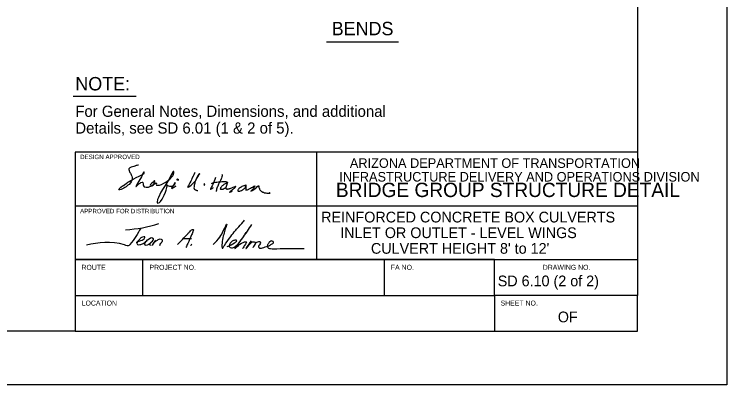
# Model space of a CAD drawing. Extents: x -0.08 to 2.83, y -0.03 to 1.92.
# Drawn here: x 2.003 to 2.833, y 0 to 0.431 of the extents above; entities that cross this region are included whole.
import ezdxf

# ---------------------------------------------------------------- set-up
doc = ezdxf.new("R2010")
doc.units = 0
for name, color, linetype in [('55', 7, 'Continuous'), ('57', 7, 'Continuous'), ('62', 7, 'Continuous'), ('63', 7, 'Continuous')]:
    doc.layers.add(name, color=color, linetype=linetype)

msp = doc.modelspace()

# ---------------------------------------------------------------- linework, layer by layer
at = {"layer": '57'}
for p, q in [((2.36678, 0.39921), (2.45047, 0.39921)), ((2.07131, 0.33607), (2.14477, 0.33607))]:
    msp.add_line(p, q, dxfattribs=at)
for points in [[(2.14765, 0.25562), (2.14682, 0.25571), (2.14575, 0.25542), (2.14487, 0.25532), (2.14398, 0.25503), (2.14311, 0.25475), (2.14203, 0.25429), (2.14043, 0.25389), (2.13901, 0.25331), (2.13813, 0.25284), (2.13758, 0.25263), (2.13706, 0.2524), (2.13655, 0.25191), (2.13637, 0.25143), (2.13634, 0.25038), (2.13646, 0.24988), (2.13669, 0.24909), (2.13707, 0.24825), (2.13754, 0.24729), (2.13802, 0.24626), (2.13848, 0.24568), (2.1391, 0.24444), (2.13948, 0.24359), (2.13985, 0.24285), (2.14011, 0.24143), (2.14019, 0.24048), (2.14006, 0.2395), (2.13967, 0.23801), (2.13887, 0.23634), (2.13823, 0.23519), (2.13663, 0.23333), (2.13514, 0.23225), (2.13328, 0.23066), (2.13172, 0.22974), (2.13035, 0.22879), (2.12878, 0.22803), (2.12732, 0.22727), (2.12575, 0.22684), (2.12502, 0.22692), (2.12462, 0.22757), (2.12482, 0.22803), (2.12536, 0.22854), (2.12583, 0.22911), (2.12687, 0.23003), (2.12901, 0.23148), (2.12993, 0.23223), (2.13153, 0.23337), (2.13326, 0.23448), (2.13516, 0.23574), (2.13681, 0.23665), (2.14133, 0.23946), (2.14564, 0.24158), (2.14763, 0.24265), (2.14977, 0.24371), (2.15138, 0.24446), (2.15266, 0.24523), (2.15357, 0.24588), (2.15395, 0.24653), (2.15403, 0.24774), (2.15357, 0.24792), (2.15339, 0.24772), (2.15326, 0.24744), (2.15189, 0.24408), (2.15104, 0.24225), (2.14793, 0.2371), (2.14615, 0.23392), (2.14537, 0.23259), (2.14456, 0.23092), (2.14471, 0.23073), (2.14621, 0.23237), (2.14786, 0.23379), (2.14933, 0.2349), (2.15041, 0.23553), (2.15025, 0.23554), (2.15166, 0.23596), (2.15233, 0.23575), (2.15248, 0.23551), (2.15292, 0.23413), (2.15298, 0.23275), (2.15347, 0.23157), (2.15416, 0.23064), (2.15662, 0.23007), (2.15903, 0.23008), (2.16063, 0.23083), (2.16326, 0.23175), (2.16493, 0.23298), (2.16588, 0.2341), (2.1662, 0.23616), (2.16645, 0.23743), (2.16619, 0.23773), (2.16568, 0.23744), (2.16444, 0.2361), (2.16299, 0.23465), (2.16243, 0.234), (2.16167, 0.23323), (2.16131, 0.23193), (2.16152, 0.23111), (2.16315, 0.23186), (2.16495, 0.23312), (2.16659, 0.23422), (2.1675, 0.23485)], [(2.1675, 0.23485), (2.16768, 0.23502), (2.16803, 0.23499), (2.16833, 0.23428), (2.16809, 0.23323), (2.1685, 0.23253), (2.16938, 0.23231), (2.17073, 0.23226), (2.17219, 0.23262), (2.17432, 0.23335), (2.17707, 0.2347), (2.17923, 0.23592), (2.18111, 0.23698), (2.18401, 0.23935), (2.18673, 0.24251), (2.1874, 0.24345), (2.18795, 0.24413), (2.18885, 0.24684), (2.18861, 0.24817), (2.18803, 0.24838), (2.18525, 0.24365), (2.18363, 0.24013), (2.17856, 0.23217), (2.17642, 0.22845), (2.17367, 0.22436), (2.17077, 0.21821), (2.16978, 0.21578), (2.16922, 0.21263), (2.16931, 0.21192), (2.17007, 0.21144), (2.17188, 0.21228), (2.17301, 0.21331), (2.17493, 0.21608), (2.17752, 0.22087), (2.17895, 0.22416), (2.17971, 0.22647), (2.18065, 0.22981), (2.18078, 0.23184), (2.18067, 0.23323), (2.18006, 0.23363), (2.17971, 0.23383), (2.17996, 0.23312), (2.18067, 0.23272), (2.18133, 0.23216), (2.18235, 0.23173), (2.18352, 0.2313), (2.18407, 0.23126), (2.18577, 0.23115), (2.18651, 0.23125), (2.18788, 0.23169), (2.18906, 0.23271), (2.18935, 0.23298), (2.19013, 0.23462), (2.19023, 0.23513), (2.18976, 0.23544), (2.18843, 0.23244), (2.1867, 0.2305), (2.18629, 0.22968), (2.18597, 0.22898), (2.18621, 0.22854), (2.18855, 0.23002), (2.18946, 0.2305), (2.19059, 0.23118), (2.19141, 0.23178)], [(2.21321, 0.24728), (2.21278, 0.24633), (2.21192, 0.2446), (2.21109, 0.24289), (2.20987, 0.24003), (2.20924, 0.23883), (2.20839, 0.23714), (2.20749, 0.23532), (2.20656, 0.23362), (2.20585, 0.23209), (2.20522, 0.23093), (2.20498, 0.23028), (2.20498, 0.22995), (2.20514, 0.22994), (2.20538, 0.22984), (2.20569, 0.22998), (2.20645, 0.23048), (2.20741, 0.23118), (2.20881, 0.23228), (2.21007, 0.23343), (2.2113, 0.23468), (2.21223, 0.23566), (2.21333, 0.23669), (2.21398, 0.23754), (2.2148, 0.23898), (2.21596, 0.24094), (2.21666, 0.24203), (2.21782, 0.24413), (2.21837, 0.24483), (2.21887, 0.24558), (2.21893, 0.24581), (2.21882, 0.24594), (2.21866, 0.246), (2.21854, 0.24593), (2.21806, 0.24521), (2.21715, 0.24405), (2.21599, 0.24204), (2.21572, 0.24131), (2.21528, 0.24042), (2.21488, 0.23963), (2.21393, 0.23749), (2.21329, 0.23598), (2.21302, 0.23478), (2.21269, 0.23374), (2.21253, 0.23244), (2.21229, 0.23068), (2.21218, 0.22945), (2.21231, 0.22828), (2.21257, 0.22781), (2.21318, 0.22732), (2.21379, 0.22691), (2.21433, 0.22667), (2.21497, 0.22648), (2.21556, 0.2264), (2.21619, 0.22636), (2.21665, 0.22637)], [(2.23711, 0.24121), (2.23674, 0.24001), (2.23642, 0.239), (2.23579, 0.23723), (2.23502, 0.23525), (2.23462, 0.2345), (2.23406, 0.23333), (2.23329, 0.23174), (2.23267, 0.23059), (2.23222, 0.22966), (2.23172, 0.22875), (2.2315, 0.22823), (2.23146, 0.2278), (2.23159, 0.22758), (2.23184, 0.22757), (2.232, 0.22763), (2.23258, 0.22801), (2.23313, 0.22838), (2.23337, 0.22858), (2.23364, 0.22878), (2.23378, 0.22887), (2.23399, 0.22905), (2.23421, 0.22928), (2.23441, 0.22947), (2.23448, 0.22961), (2.23467, 0.22983)], [(2.24473, 0.24483), (2.24497, 0.24428), (2.24498, 0.24372), (2.24493, 0.24321), (2.24468, 0.24225), (2.24431, 0.24076), (2.24388, 0.23971), (2.24318, 0.23801), (2.24267, 0.23695), (2.24213, 0.23588), (2.24099, 0.23343), (2.24057, 0.23259), (2.23951, 0.23037), (2.23933, 0.22998), (2.23898, 0.22908), (2.23857, 0.22768), (2.23835, 0.22672), (2.23821, 0.22563), (2.23811, 0.22523)], [(2.19468, 0.23875), (2.1943, 0.23878), (2.19381, 0.23888), (2.19338, 0.23913), (2.19307, 0.23928), (2.19284, 0.23933), (2.19253, 0.23933), (2.19238, 0.23916), (2.1922, 0.23895), (2.19217, 0.23886), (2.19224, 0.23861), (2.19245, 0.23854), (2.19273, 0.23851), (2.19302, 0.23849), (2.1935, 0.23855), (2.19382, 0.23856), (2.19419, 0.23856), (2.19455, 0.23867), (2.19471, 0.23872)], [(2.22443, 0.23244), (2.22472, 0.23308), (2.2246, 0.23376), (2.22436, 0.23406), (2.22408, 0.23412), (2.22398, 0.23393), (2.22388, 0.23324), (2.224, 0.23256), (2.22423, 0.23234), (2.22434, 0.2322), (2.22443, 0.23224), (2.2244, 0.23238)], [(2.23248, 0.23456), (2.23325, 0.23476), (2.2342, 0.23501), (2.23568, 0.23543), (2.23742, 0.23576), (2.23878, 0.23593), (2.24092, 0.23616), (2.24296, 0.23643), (2.24483, 0.23658), (2.24631, 0.23661), (2.24751, 0.23662), (2.24815, 0.23658), (2.24954, 0.23651), (2.25052, 0.23638), (2.25088, 0.23621), (2.25113, 0.23568), (2.2507, 0.2337), (2.25061, 0.23341), (2.25006, 0.23176), (2.24968, 0.23083), (2.24923, 0.2298), (2.24903, 0.22937), (2.24881, 0.22913), (2.24855, 0.22885), (2.24788, 0.22845), (2.24669, 0.22782), (2.24572, 0.22757), (2.24486, 0.22728), (2.24453, 0.22723), (2.24402, 0.22721), (2.24346, 0.22738), (2.24333, 0.22753), (2.24326, 0.22773), (2.24329, 0.22813), (2.24333, 0.22875), (2.24351, 0.22929), (2.24369, 0.22982), (2.24413, 0.23055), (2.24473, 0.23118), (2.24562, 0.23205), (2.24626, 0.23258), (2.24677, 0.23295), (2.24743, 0.23348), (2.24812, 0.23387), (2.24898, 0.23437), (2.24957, 0.23468), (2.25026, 0.23503), (2.25053, 0.23503), (2.25075, 0.23493), (2.25082, 0.23468), (2.25057, 0.23343), (2.25053, 0.23315), (2.25026, 0.23215), (2.24986, 0.23102), (2.2495, 0.23), (2.24939, 0.2295), (2.24935, 0.22926), (2.24932, 0.22911), (2.24933, 0.22867), (2.24944, 0.22839), (2.24977, 0.2281), (2.2499, 0.22803), (2.25012, 0.22803), (2.2505, 0.22796), (2.25113, 0.22796), (2.25153, 0.22798), (2.25188, 0.22807), (2.25251, 0.22818), (2.25313, 0.22828), (2.25369, 0.22836), (2.25436, 0.22853), (2.25515, 0.22883), (2.25633, 0.22935), (2.25781, 0.22992), (2.25893, 0.23036), (2.25968, 0.23067), (2.26019, 0.23098), (2.2608, 0.23112), (2.26094, 0.23098), (2.26057, 0.23036), (2.26004, 0.22976), (2.25931, 0.22903), (2.25887, 0.22862), (2.25828, 0.22803), (2.25718, 0.22698), (2.25408, 0.22424), (2.25384, 0.22398), (2.25413, 0.22412), (2.25504, 0.22455), (2.25579, 0.22489), (2.25632, 0.22513), (2.25663, 0.22528)], [(2.27233, 0.23026), (2.27212, 0.2318), (2.27153, 0.23226), (2.27104, 0.23214), (2.26923, 0.23137), (2.2681, 0.23077), (2.26717, 0.23022), (2.26638, 0.22968), (2.26546, 0.22897), (2.26466, 0.22842), (2.26423, 0.22782), (2.26369, 0.2272), (2.26337, 0.22659), (2.26336, 0.22625), (2.26337, 0.22586), (2.26366, 0.22562), (2.26398, 0.22548), (2.26441, 0.22542), (2.26464, 0.22542), (2.26516, 0.22547), (2.26554, 0.22556), (2.2664, 0.22583), (2.26779, 0.22633), (2.26861, 0.22685), (2.26952, 0.22746), (2.27029, 0.22808), (2.27109, 0.22873), (2.27183, 0.22942), (2.27243, 0.23006), (2.27312, 0.23148), (2.27319, 0.23218), (2.27303, 0.23268), (2.27271, 0.23234), (2.27258, 0.23171), (2.27262, 0.23101), (2.27263, 0.22988), (2.27258, 0.22914), (2.27257, 0.22827), (2.27259, 0.22769), (2.27259, 0.22686), (2.27266, 0.22673), (2.27281, 0.22671), (2.27373, 0.22695), (2.27465, 0.22718), (2.27539, 0.22753), (2.2761, 0.22788), (2.27641, 0.22803), (2.27723, 0.22842), (2.27798, 0.22885), (2.27917, 0.22956), (2.28043, 0.2302), (2.28166, 0.23094), (2.28213, 0.23122), (2.28297, 0.23177), (2.28313, 0.23174), (2.28293, 0.23104), (2.28261, 0.23033), (2.28215, 0.22959), (2.28155, 0.22873), (2.28111, 0.22811), (2.27994, 0.22684), (2.27862, 0.22555), (2.27853, 0.22532), (2.27868, 0.22528), (2.28006, 0.22628), (2.28188, 0.22757), (2.28343, 0.22858), (2.28454, 0.22938), (2.28567, 0.23033), (2.28698, 0.23175), (2.28705, 0.23179), (2.28728, 0.23206), (2.28742, 0.23198), (2.28766, 0.23069), (2.2879, 0.22988), (2.28822, 0.22903), (2.28848, 0.22836), (2.28878, 0.22766), (2.28907, 0.22713), (2.28958, 0.22627), (2.28999, 0.22582), (2.29046, 0.22545), (2.29094, 0.22511), (2.29132, 0.22488), (2.29228, 0.2244), (2.29317, 0.22411), (2.29438, 0.22369), (2.29511, 0.22358), (2.29611, 0.22335), (2.29699, 0.22325), (2.29795, 0.22323), (2.29877, 0.22316), (2.29951, 0.22312), (2.30051, 0.22297), (2.30093, 0.22293), (2.30071, 0.22307), (2.30038, 0.22326), (2.30007, 0.22348), (2.29987, 0.2236)]]:
    msp.add_lwpolyline(points, dxfattribs=at)
msp.add_arc((2.12576, 0.32651), 0.14607, 272.67102, 288.18495, dxfattribs=at)
msp.add_ellipse((2.1597, 0.16674), major_axis=(0.00445, 0.00414), ratio=0.425517, dxfattribs=at)
for points in [[(2.23468, 0.16329), (2.24247, 0.17206), (2.2468, 0.17993), (2.25055, 0.18688), (2.24978, 0.18448), (2.24873, 0.18168), (2.24786, 0.17853), (2.24593, 0.17117), (2.24575, 0.15925), (2.24768, 0.16223), (2.25383, 0.17108), (2.25913, 0.17799), (2.26284, 0.18217), (2.26953, 0.18973), (2.27125, 0.19154)], [(2.27913, 0.18645), (2.26691, 0.16866), (2.26002, 0.15884), (2.27102, 0.16638), (2.27174, 0.16649), (2.27323, 0.16633), (2.27308, 0.16531), (2.27148, 0.1627), (2.26896, 0.15855)], [(2.15026, 0.18245), (2.13747, 0.1632), (2.13658, 0.16231), (2.13123, 0.16275), (2.08684, 0.16261)], [(2.19315, 0.16345), (2.19896, 0.16933), (2.20501, 0.17574), (2.20724, 0.17819), (2.20941, 0.1803), (2.21138, 0.18096), (2.2113, 0.17937), (2.21077, 0.17794), (2.20906, 0.17363), (2.20497, 0.16464), (2.20276, 0.16)], [(2.25098, 0.16082), (2.25957, 0.16531), (2.26102, 0.16633), (2.26204, 0.16779), (2.26175, 0.16822), (2.26001, 0.16837), (2.25666, 0.16706), (2.25405, 0.16415), (2.25332, 0.16197), (2.25332, 0.16095), (2.25581, 0.15961), (2.26008, 0.16091), (2.26408, 0.1646), (2.27308, 0.1773)], [(2.14468, 0.16595), (2.15189, 0.16856), (2.15402, 0.16987), (2.155, 0.1715), (2.155, 0.17216), (2.15369, 0.17232), (2.15108, 0.1715), (2.1483, 0.16889), (2.1465, 0.16676), (2.14569, 0.16464), (2.14634, 0.16333), (2.14912, 0.16317), (2.15298, 0.16457), (2.15512, 0.16583), (2.15712, 0.16742), (2.15716, 0.16742)], [(2.16416, 0.17088), (2.16467, 0.1696), (2.16316, 0.16671), (2.16115, 0.16432), (2.16077, 0.16281), (2.16153, 0.16206)], [(2.16731, 0.16847), (2.16582, 0.16612), (2.16341, 0.16218), (2.16591, 0.16562), (2.16907, 0.16797), (2.17045, 0.16897), (2.17488, 0.16916), (2.17524, 0.16783), (2.17478, 0.16626), (2.17294, 0.16391), (2.17196, 0.1618)], [(2.20019, 0.17022), (2.20269, 0.17029), (2.20533, 0.17015), (2.20922, 0.17029)], [(2.27878, 0.16743), (2.27342, 0.15912), (2.27381, 0.15951), (2.27965, 0.16591), (2.28139, 0.16656), (2.28339, 0.16597), (2.28369, 0.16421), (2.28271, 0.16235), (2.28114, 0.1599), (2.28349, 0.16333), (2.28546, 0.166), (2.28955, 0.16646), (2.28936, 0.16401), (2.28761, 0.1603), (2.28796, 0.15989), (2.28878, 0.1592), (2.29346, 0.1599), (2.29972, 0.16196), (2.30275, 0.16362), (2.30493, 0.16569), (2.30353, 0.16734), (2.30001, 0.16587), (2.29825, 0.16323), (2.29786, 0.16235), (2.29776, 0.16049), (2.30158, 0.15863), (2.30871, 0.15844), (2.34054, 0.15879)], [(2.20987, 0.16382), (2.20906, 0.16268), (2.20808, 0.16202)]]:
    msp.add_spline(points, degree=3, dxfattribs=at)
at = {"layer": '63'}
for p, q in [((2.83333, 1.83333), (2.83333, 0)), ((2.72918, 0.27077), (2.07387, 0.27077)), ((2.07387, 0.27077), (2.07387, 0.06244)), ((2.35493, 0.27077), (2.35493, 0.14578)), ((2.57284, 0.27077), (2.57284, 0.27077)), ((2.07387, 0.20828), (2.72918, 0.20828)), ((2.07387, 0.20647), (2.07387, 0.20647)), ((2.07387, 0.20647), (2.07387, 0.20647)), ((2.07387, 0.14578), (2.72918, 0.14578)), ((2.07387, 0.14397), (2.07387, 0.14397)), ((2.08908, 0.14583), (2.08931, 0.14583)), ((2.15266, 0.10411), (2.15266, 0.14578)), ((2.23742, 0.14583), (2.23742, 0.14583)), ((2.23742, 0.14583), (2.23742, 0.14583)), ((2.23742, 0.14583), (2.23742, 0.14583)), ((2.23742, 0.14583), (2.23742, 0.14583)), ((2.43435, 0.10411), (2.43435, 0.14578)), ((2.07387, 0.10411), (2.56251, 0.10411)), ((2.56251, 0.10411), (2.56251, 0.06244)), ((2.72918, 0.06244), (2.72918, 0.10411)), ((2.07387, 0.06244), (2.72918, 0.06244)), ((2.83333, 0), (0, 0)), ((2.83, 0.00033), (2.83, 0.00033))]:
    msp.add_line(p, q, dxfattribs=at)
msp.add_lwpolyline([(0.16668, 0.06244), (0.16668, 1.77077), (2.72918, 1.77077), (2.72918, 0.10411), (2.56251, 0.10411), (2.56251, 0.14578), (2.07387, 0.14578), (2.07387, 0.06244)], close=True, dxfattribs=at)

# ---------------------------------------------------------------- texts
at = {"layer": '55'}
for s, p in [('DESIGN APPROVED', (2.07944, 0.26274)), ('APPROVED FOR DISTRIBUTION', (2.07944, 0.19966))]:
    msp.add_text(s, height=0.0052084, dxfattribs=at).set_placement(p)
at = {"layer": '57'}
for s, height, p in [('BENDS', 0.015625, (2.37277, 0.40702)), ('NOTE:', 0.015625, (2.07387, 0.34278)), ('For General Notes, Dimensions, and additional', 0.0130208, (2.07387, 0.31201)), ('Details, see SD 6.01 (1 & 2 of 5).', 0.0130208, (2.07387, 0.29248))]:
    msp.add_text(s, height=height, dxfattribs=at).set_placement(p)
at = {"layer": '62'}
for s, p in [('REINFORCED CONCRETE BOX CULVERTS', (2.3605, 0.189)), ('INLET OR OUTLET - LEVEL WINGS', (2.38266, 0.17078)), ("CULVERT HEIGHT 8' to 12'", (2.41851, 0.15255)), ('SD 6.10 (2 of 2)', (2.56631, 0.11464))]:
    msp.add_text(s, height=0.0125, dxfattribs=at).set_placement(p)
at = {"layer": '63'}
for s, height, p in [('ARIZONA DEPARTMENT OF TRANSPORTATION', 0.0111083, (2.39394, 0.25258)), ('INFRASTRUCTURE DELIVERY AND OPERATIONS DIVISION', 0.0111083, (2.38162, 0.23663)), ('BRIDGE GROUP STRUCTURE DETAIL', 0.0166667, (2.37762, 0.2186)), ('ROUTE', 0.005833, (2.08105, 0.13383)), ('PROJECT NO.', 0.0058333, (2.16034, 0.13383)), ('FA NO.', 0.005833, (2.44175, 0.13383)), ('DRAWING NO.', 0.0058334, (2.61888, 0.13383)), ('LOCATION', 0.005833, (2.08128, 0.09217)), ('SHEET NO.', 0.005833, (2.56964, 0.09217)), ('OF', 0.0125, (2.63638, 0.0727))]:
    msp.add_text(s, height=height, dxfattribs=at).set_placement(p)

doc.saveas('drawing.dxf')
